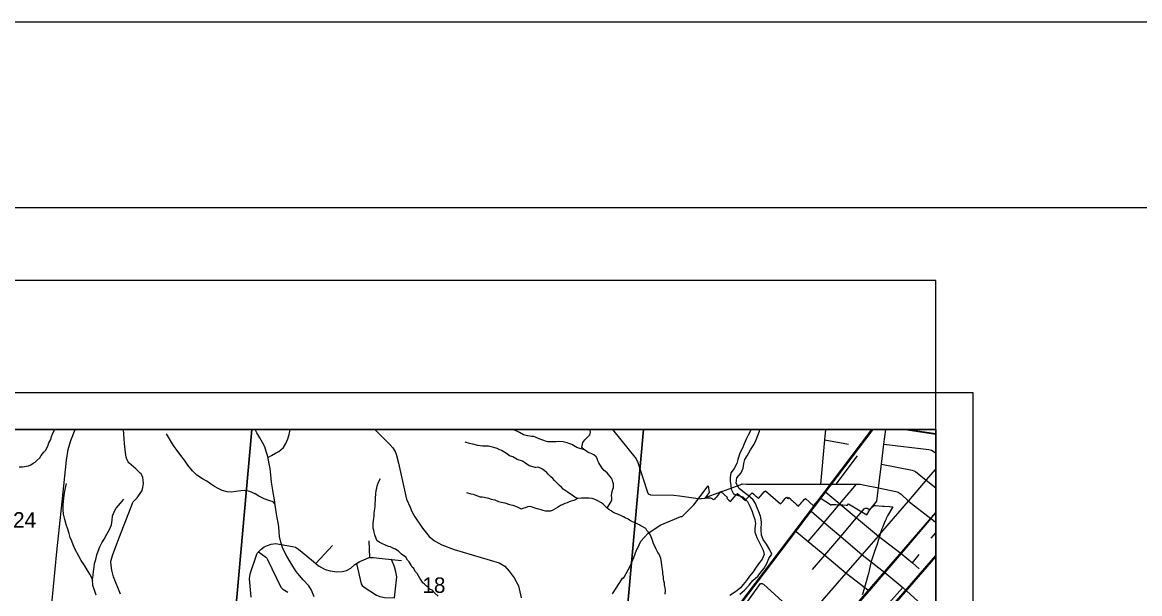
# Model space of a CAD drawing. Extents: x -8.2 to 38.5, y -0.1 to 21.9.
# Drawn here: x 6.498 to 9.514, y 20.321 to 21.864 of the extents above; entities that cross this region are included whole.
import ezdxf

# ---------------------------------------------------------------- set-up
doc = ezdxf.new("R2010")
doc.units = 0
for name, color, linetype in [('Default', 7, 'Continuous'), ('GM_X_Airport_Location_Class_1', 7, 'Continuous'), ('GM_X_County', 7, 'Continuous'), ('GM_X_County_Road_Text', 7, 'Continuous'), ('GM_X_Minor_River', 7, 'Continuous'), ('GM_X_Section', 7, 'Continuous'), ('GM_X_Township', 7, 'Continuous'), ('GM_X_Township_Subdivision_Text', 7, 'Continuous'), ('GM_X_Township_Text', 7, 'Continuous'), ('GM_X_US_Location', 7, 'Continuous')]:
    doc.layers.add(name, color=color, linetype=linetype)

msp = doc.modelspace()

# ---------------------------------------------------------------- linework, layer by layer
at = {"layer": 'Default'}
for points in [[(8.9634, 15.7165), (8.9634, 21.1673), (3.5768, 21.1673)], [(8.9634, 15.3136), (8.9634, 20.7535), (8.8842, 20.7645), (4.0666, 20.7645), (4.0665, 20.7635), (4.0467, 20.5533), (4.0404, 20.4649), (4.0302, 20.3597), (3.9961, 19.9817), (3.9436, 19.3979), (3.9289, 19.2353), (3.8854, 18.7517), (3.8472, 18.3279), (3.8449, 18.303), (3.8435, 18.2895), (3.8184, 18.0516), (3.7486, 17.3899)], [(8.091, 20.3209), (8.1173, 20.3612), (8.1189, 20.3639), (8.1204, 20.3632), (8.1223, 20.3664), (8.1391, 20.3959), (8.1483, 20.4192), (8.1558, 20.4393), (8.1564, 20.4405), (8.1588, 20.4438), (8.1679, 20.4634), (8.1875, 20.4849), (8.216, 20.504), (8.2199, 20.5066), (8.2759, 20.53), (8.2793, 20.5296), (8.3103, 20.5618), (8.3495, 20.6123), (8.3518, 20.5951), (8.3409, 20.5807), (8.3556, 20.5799), (8.3582, 20.5797), (8.3635, 20.5762), (8.365, 20.578), (8.3676, 20.5763), (8.3704, 20.5801), (8.3733, 20.5839), (8.3768, 20.5885), (8.3802, 20.593), (8.3837, 20.5975), (8.4013, 20.5816), (8.3996, 20.5793), (8.405, 20.5744), (8.4092, 20.5706), (8.425, 20.5883), (8.4285, 20.592), (8.4497, 20.5735), (8.4523, 20.5763), (8.4681, 20.594), (8.4724, 20.5902), (8.4766, 20.5864), (8.4808, 20.5826), (8.485, 20.5788), (8.5008, 20.5964), (8.5037, 20.5996), (8.5442, 20.5642), (8.5472, 20.5672), (8.5504, 20.5707), (8.5536, 20.5742), (8.5574, 20.5784), (8.5605, 20.5819), (8.5647, 20.578), (8.5673, 20.5809), (8.5713, 20.5773), (8.5716, 20.5771), (8.5737, 20.5752), (8.5758, 20.5733), (8.58, 20.5694), (8.5821, 20.5675), (8.5842, 20.5656), (8.5856, 20.5643), (8.5884, 20.5618), (8.5927, 20.5579), (8.5959, 20.5614), (8.599, 20.565), (8.6022, 20.5685), (8.6054, 20.572), (8.6086, 20.5755), (8.6116, 20.5786), (8.6336, 20.5591), (8.6526, 20.5799), (8.6568, 20.5767), (8.6772, 20.5637), (8.6816, 20.5608), (8.683, 20.5624), (8.6875, 20.5622), (8.6937, 20.5619), (8.7002, 20.5616), (8.7061, 20.5613), (8.7126, 20.561), (8.722, 20.5605), (8.7251, 20.5604), (8.7283, 20.5642), (8.7774, 20.534), (8.7804, 20.5385), (8.7868, 20.5499), (8.7971, 20.5596), (8.8013, 20.5594), (8.8196, 20.5582), (8.8244, 20.5578), (8.8384, 20.5569), (8.8474, 20.5563), (8.8331, 20.5318), (8.8299, 20.5241), (8.8287, 20.5211), (8.8285, 20.5206), (8.8243, 20.5124), (8.824, 20.5117), (8.8208, 20.5018), (8.8183, 20.4962), (8.8147, 20.4854), (8.8115, 20.4755), (8.8082, 20.4655), (8.805, 20.4555), (8.8017, 20.4454), (8.7985, 20.4356), (8.7896, 20.4082), (8.7869, 20.3963), (8.7824, 20.3757), (8.7822, 20.3758), (8.7785, 20.364), (8.7782, 20.3631), (8.7692, 20.3316), (8.7666, 20.3224), (8.7646, 20.3182)]]:
    msp.add_lwpolyline(points, dxfattribs=at)
for points in [[(7.1182, 20.7645), (6.1116, 20.7645), (6.0401, 20.072), (7.0485, 19.9899)], [(8.1752, 20.7645), (7.1182, 20.7645), (7.0485, 19.9899), (8.0944, 19.8749)], [(8.8806, 20.7645), (8.1752, 20.7645), (8.0944, 19.8749), (8.9634, 19.7388), (8.9634, 20.7526)], [(8.9634, 20.7526), (8.9634, 20.7645), (8.8806, 20.7645)], [(8.9634, 20.7535), (8.9634, 20.7645), (8.8842, 20.7645)]]:
    msp.add_lwpolyline(points, close=True, dxfattribs=at)
at = {"layer": 'GM_X_Airport_Location_Class_1'}
msp.add_line((8.9634, 20.5125), (8.9498, 20.5244), dxfattribs=at)
at = {"layer": 'GM_X_County'}
msp.add_lwpolyline([(1.5634, 21.3645), (33.5634, 21.3645), (33.5634, 0.3645), (1.5634, 0.3645)], close=True, dxfattribs=at)
at = {"layer": 'GM_X_Minor_River'}
msp.add_line((8.465, 20.7645), (8.4575, 20.7492), dxfattribs=at)
for points in [[(6.5496, 20.6947), (6.5563, 20.7033), (6.5614, 20.7092), (6.5635, 20.7138), (6.5674, 20.7201), (6.5699, 20.7284), (6.5751, 20.7382), (6.5773, 20.7461), (6.5813, 20.7566), (6.5859, 20.7645)], [(7.1801, 20.5644), (7.1755, 20.5696), (7.1634, 20.5733), (7.151, 20.5774), (7.1371, 20.585), (7.127, 20.5913), (7.1123, 20.5977), (7.0979, 20.6), (7.0881, 20.5995), (7.0743, 20.5975), (7.0625, 20.5959), (7.0515, 20.5962), (7.0379, 20.6003), (7.0267, 20.6059), (7.0169, 20.6111), (7.0064, 20.6182), (6.996, 20.6253), (6.9843, 20.6317), (6.9698, 20.6415), (6.9575, 20.6536), (6.9453, 20.6687), (6.9358, 20.6819), (6.9266, 20.695), (6.9163, 20.7078), (6.9085, 20.7191), (6.9019, 20.7291), (6.8957, 20.7395), (6.8877, 20.753)], [(7.2856, 20.3133), (7.2792, 20.331), (7.2719, 20.3429), (7.2563, 20.3593), (7.2467, 20.3702), (7.2371, 20.3818), (7.2283, 20.3961), (7.221, 20.4077), (7.2126, 20.4227), (7.2057, 20.4347), (7.2007, 20.4466), (7.1957, 20.4604), (7.1926, 20.476), (7.1914, 20.4886), (7.1902, 20.5016), (7.1886, 20.5141), (7.1866, 20.5267), (7.1846, 20.5374), (7.1826, 20.5489), (7.1806, 20.5611), (7.1787, 20.5745), (7.1764, 20.5893), (7.1744, 20.6012), (7.1727, 20.6122), (7.1711, 20.6225), (7.1698, 20.6328), (7.1689, 20.6424), (7.1674, 20.6591), (7.165, 20.6717), (7.163, 20.682), (7.1599, 20.695), (7.1567, 20.7054), (7.1528, 20.7176), (7.1467, 20.7296), (7.1394, 20.7427), (7.1317, 20.7562), (7.1268, 20.7645)], [(7.1613, 20.6893), (7.1709, 20.6948), (7.1813, 20.701), (7.1909, 20.7057), (7.2034, 20.7164), (7.2093, 20.7269), (7.2146, 20.7393), (7.2183, 20.751), (7.2209, 20.7643), (7.2209, 20.7645)], [(7.8789, 20.7455), (7.8725, 20.746), (7.8585, 20.7487), (7.8506, 20.7508), (7.8401, 20.7565), (7.8352, 20.7593), (7.8251, 20.7637), (7.8236, 20.7645)], [(8.0764, 20.5527), (8.0873, 20.5701), (8.089, 20.5746), (8.0892, 20.5799), (8.0887, 20.5864), (8.0894, 20.5928), (8.0903, 20.5977), (8.0924, 20.6033), (8.0934, 20.6079), (8.094, 20.6132), (8.0938, 20.6177), (8.0921, 20.6235), (8.0905, 20.6304), (8.0847, 20.6379), (8.0807, 20.6437), (8.0763, 20.6477), (8.0682, 20.6541), (8.0635, 20.66), (8.0603, 20.6651), (8.0571, 20.6705), (8.0546, 20.6752), (8.0518, 20.6803), (8.0504, 20.6849), (8.0472, 20.6911), (8.0406, 20.6967), (8.0358, 20.6992), (8.0309, 20.7009), (8.0257, 20.703), (8.0212, 20.7059), (8.0168, 20.7091), (8.0124, 20.7127), (8.0088, 20.7174), (8.0102, 20.7249), (8.0111, 20.7295), (8.0163, 20.7365), (8.0207, 20.7412), (8.0258, 20.7456), (8.0298, 20.7503), (8.0316, 20.7575), (8.0307, 20.7632), (8.0304, 20.7645)], [(8.4575, 20.7492), (8.452, 20.7387), (8.4461, 20.7258), (8.4417, 20.7141), (8.435, 20.701), (8.4298, 20.684), (8.4269, 20.6734), (8.4198, 20.6598), (8.4105, 20.6482), (8.4087, 20.635), (8.4089, 20.6251), (8.4102, 20.6137), (8.4116, 20.6034), (8.4174, 20.5911), (8.4306, 20.5867), (8.4427, 20.583), (8.4557, 20.5702), (8.462, 20.558), (8.4678, 20.5438), (8.471, 20.5342), (8.4753, 20.522), (8.4774, 20.5113), (8.4749, 20.4977), (8.4751, 20.4874), (8.4805, 20.4736), (8.4864, 20.4621), (8.4926, 20.4498), (8.4977, 20.4391), (8.5001, 20.4269), (8.4953, 20.4144), (8.4852, 20.4017), (8.4774, 20.3908), (8.4708, 20.3807), (8.4611, 20.3687), (8.4525, 20.3567), (8.4436, 20.3466), (8.4362, 20.3369), (8.4231, 20.3265), (8.4081, 20.3165)], [(8.4348, 20.3198), (8.4475, 20.3314), (8.4599, 20.3448), (8.47, 20.3572), (8.4831, 20.3687), (8.4924, 20.3807), (8.5002, 20.3908), (8.5073, 20.4032), (8.5132, 20.4164), (8.5214, 20.4284), (8.5159, 20.4403), (8.5067, 20.4549), (8.4975, 20.4676), (8.4931, 20.4791), (8.4919, 20.4935), (8.493, 20.5156), (8.4903, 20.5308), (8.4859, 20.5423), (8.4816, 20.5534), (8.4769, 20.5649), (8.4706, 20.5749), (8.4576, 20.5869), (8.4426, 20.5975), (8.4329, 20.6056), (8.4248, 20.6195), (8.4269, 20.6346), (8.4386, 20.6477), (8.4437, 20.6601), (8.4459, 20.673), (8.4487, 20.6836), (8.4542, 20.6938), (8.4636, 20.7103), (8.4734, 20.7253), (8.4789, 20.7366), (8.4833, 20.7483), (8.4877, 20.7608), (8.4891, 20.7645)], [(7.8831, 20.6618), (7.8662, 20.6663), (7.8535, 20.6754), (7.8479, 20.679), (7.8343, 20.6839), (7.822, 20.6907), (7.8133, 20.694), (7.8051, 20.7003), (7.7912, 20.7083), (7.7867, 20.71), (7.7796, 20.7132), (7.7709, 20.7165), (7.7569, 20.7196), (7.7478, 20.7202), (7.7406, 20.72), (7.7341, 20.7206), (7.7281, 20.7215), (7.7145, 20.725), (7.705, 20.7267), (7.6937, 20.7305)], [(8.0159, 20.7098), (8.0029, 20.7131), (7.995, 20.7164), (7.9906, 20.7189), (7.9813, 20.7239), (7.9734, 20.7272), (7.9689, 20.7289), (7.9576, 20.7313), (7.9451, 20.7322), (7.9394, 20.7317), (7.9322, 20.7316), (7.9272, 20.7314), (7.9162, 20.7319), (7.9106, 20.7332), (7.9057, 20.735), (7.9004, 20.7367), (7.893, 20.7397), (7.8789, 20.7455)], [(6.4895, 20.6637), (6.4986, 20.6642), (6.5043, 20.6648), (6.5097, 20.6654), (6.515, 20.6671), (6.5212, 20.6693), (6.5278, 20.6736), (6.5332, 20.6765), (6.5375, 20.6814), (6.5457, 20.688), (6.5496, 20.6947)], [(7.9983, 20.5783), (7.9901, 20.5814), (7.985, 20.5854), (7.9776, 20.5906), (7.9691, 20.5967), (7.9635, 20.6003), (7.9579, 20.6036), (7.9536, 20.6087), (7.9481, 20.6139), (7.9422, 20.6198), (7.9349, 20.627), (7.9298, 20.6329), (7.9247, 20.6369), (7.9173, 20.6441), (7.9126, 20.6492), (7.9074, 20.6532), (7.9019, 20.6576), (7.8952, 20.6609), (7.8899, 20.6627), (7.8818, 20.6616)], [(7.6209, 20.3146), (7.6116, 20.3225), (7.6043, 20.3307), (7.5983, 20.3339), (7.5938, 20.3389), (7.5882, 20.3425), (7.5842, 20.3476), (7.5797, 20.3504), (7.5764, 20.355), (7.5709, 20.3636), (7.5636, 20.3756), (7.5588, 20.3814), (7.5549, 20.3895), (7.5504, 20.3934), (7.5479, 20.3985), (7.5424, 20.4077), (7.538, 20.4121), (7.5333, 20.4198), (7.5213, 20.4281), (7.5147, 20.4355), (7.5057, 20.4415), (7.4982, 20.4444), (7.4922, 20.4476), (7.4865, 20.4493), (7.4782, 20.4529), (7.47, 20.4562), (7.461, 20.461), (7.4554, 20.465), (7.4532, 20.4708), (7.4501, 20.48), (7.448, 20.4873), (7.447, 20.4919), (7.4456, 20.4988), (7.4456, 20.5121), (7.4462, 20.5182), (7.4467, 20.5254), (7.4476, 20.5307), (7.4482, 20.539), (7.4491, 20.5439), (7.4497, 20.5515), (7.4502, 20.5565), (7.4508, 20.5652), (7.4515, 20.5743), (7.4512, 20.5797), (7.4527, 20.591), (7.4533, 20.5998), (7.455, 20.6062), (7.4559, 20.6123), (7.4584, 20.6202), (7.4612, 20.6258), (7.4648, 20.6326)], [(6.6883, 20.3571), (6.6875, 20.3603), (6.6802, 20.3741), (6.6736, 20.3857), (6.6649, 20.3996), (6.6575, 20.4115), (6.6499, 20.4247), (6.6415, 20.4393), (6.6354, 20.4531), (6.6322, 20.4631), (6.6279, 20.4735), (6.6247, 20.4842), (6.6212, 20.4957), (6.6166, 20.508), (6.6127, 20.5214), (6.6096, 20.5359), (6.6084, 20.5481), (6.6087, 20.561), (6.6093, 20.5705), (6.6103, 20.58), (6.6118, 20.5925), (6.6139, 20.6027), (6.6177, 20.6193)], [(7.6973, 20.5949), (7.709, 20.5911), (7.7154, 20.5898), (7.7199, 20.5885), (7.7267, 20.5853), (7.7343, 20.5832), (7.7392, 20.5827), (7.7452, 20.5817), (7.7566, 20.5795), (7.7634, 20.5767), (7.7739, 20.5745), (7.7834, 20.5708), (7.7913, 20.5686), (7.8004, 20.5669), (7.8132, 20.5627), (7.8219, 20.5606), (7.8335, 20.5557), (7.8448, 20.5504), (7.8618, 20.5563)], [(6.6978, 20.317), (6.6928, 20.3309), (6.689, 20.3435), (6.6882, 20.3595), (6.6892, 20.3709), (6.6907, 20.3822), (6.692, 20.3921), (6.6934, 20.4027), (6.6964, 20.414), (6.6997, 20.4261), (6.703, 20.4363), (6.7078, 20.4483), (6.713, 20.4588), (6.719, 20.4686), (6.7265, 20.4821), (6.734, 20.4945), (6.7393, 20.5072), (6.7407, 20.5201), (6.7421, 20.5307), (6.7454, 20.5409), (6.7521, 20.5526), (6.7631, 20.5656), (6.7725, 20.5771)], [(8.2337, 20.3205), (8.2341, 20.33), (8.2333, 20.3376), (8.2317, 20.3449), (8.2311, 20.3498), (8.2298, 20.3564), (8.2292, 20.3609), (8.2287, 20.367), (8.2272, 20.3755), (8.2266, 20.3804), (8.2257, 20.3865), (8.2251, 20.3919), (8.2239, 20.3995), (8.2234, 20.4053), (8.2221, 20.4121), (8.2216, 20.4167), (8.2191, 20.4233), (8.2174, 20.4279), (8.2135, 20.433), (8.211, 20.4381), (8.2078, 20.4435), (8.2054, 20.4501), (8.2022, 20.4563), (8.2002, 20.4625), (8.197, 20.4702), (8.1957, 20.4752), (8.1915, 20.483), (8.1886, 20.4876), (8.1842, 20.492), (8.181, 20.4974), (8.168, 20.5044), (8.1628, 20.5073), (8.1542, 20.5115), (8.1452, 20.5156), (8.1374, 20.5198), (8.133, 20.5226), (8.1255, 20.526), (8.1211, 20.5288), (8.1155, 20.5317), (8.1087, 20.5346), (8.1024, 20.5368), (8.0975, 20.5385), (8.0923, 20.5414), (8.0875, 20.545), (8.0808, 20.5491), (8.0764, 20.5527), (8.0713, 20.5582), (8.0658, 20.5634), (8.061, 20.5666), (8.0513, 20.5724), (8.0416, 20.5766), (8.036, 20.5787), (8.0269, 20.5795), (8.0223, 20.5793), (8.014, 20.5796), (8.0075, 20.5795), (7.9964, 20.5781), (7.991, 20.5749), (7.9744, 20.5691), (7.969, 20.5667), (7.9621, 20.5647), (7.9571, 20.5626), (7.9505, 20.5598), (7.9423, 20.5545), (7.9361, 20.5509), (7.9299, 20.547), (7.9241, 20.5442), (7.9191, 20.544), (7.91, 20.5444), (7.9036, 20.5462), (7.8984, 20.5483), (7.8927, 20.5497), (7.8882, 20.5506), (7.8826, 20.5528), (7.8773, 20.5545), (7.8725, 20.5559), (7.8668, 20.5565), (7.8618, 20.5563)]]:
    msp.add_lwpolyline(points, dxfattribs=at)
at = {"layer": 'GM_X_Section'}
msp.add_lwpolyline([(0.0634, -0.1355), (34.0634, -0.1355), (34.0634, 21.8645), (0.0634, 21.8645)], close=True, dxfattribs=at)
msp.add_lwpolyline([(8.9634, 15.3136), (8.9634, 20.7645), (2.1634, 20.7645), (2.1634, 13.9645)], dxfattribs=at)
at = {"layer": 'GM_X_Township'}
for p, q in [((2.0634, 20.8645), (9.0634, 20.8645)), ((9.0634, 20.8645), (9.0634, 13.8645)), ((2.1634, 20.7645), (8.9634, 20.7645)), ((8.9634, 20.7645), (8.9634, 13.9645))]:
    msp.add_line(p, q, dxfattribs=at)
at = {"layer": 'GM_X_Township_Subdivision_Text'}
for p, q in [((8.6642, 20.7371), (8.7282, 20.7256)), ((8.6944, 20.617), (8.7527, 20.6936)), ((8.951, 20.4715), (8.9634, 20.4858)), ((7.2908, 20.4028), (7.3359, 20.4514)), ((7.4358, 20.4189), (7.434, 20.4641)), ((8.9004, 20.4046), (8.9187, 20.4274))]:
    msp.add_line(p, q, dxfattribs=at)
for points in [[(6.7631, 20.32), (6.7447, 20.3674), (6.7399, 20.3854), (6.738, 20.3987), (6.7372, 20.4062), (6.7374, 20.409), (6.7378, 20.4118), (6.743, 20.4275), (6.7608, 20.4752), (6.7966, 20.568), (6.7977, 20.5698), (6.8068, 20.5782), (6.8087, 20.5805), (6.8197, 20.5971), (6.8214, 20.5999), (6.824, 20.6086), (6.8254, 20.6192), (6.8248, 20.6276), (6.8236, 20.6352), (6.8221, 20.6395), (6.8204, 20.6429), (6.819, 20.6448), (6.8164, 20.6472), (6.8049, 20.6585), (6.7857, 20.6752), (6.7838, 20.6774), (6.7811, 20.6832), (6.7789, 20.6901), (6.7766, 20.703), (6.7739, 20.7274), (6.771, 20.7645)], [(8.6305, 20.3864), (8.6638, 20.4254), (8.707, 20.476), (8.7499, 20.5262), (8.7712, 20.5511), (8.7719, 20.5517), (8.7734, 20.5524), (8.775, 20.5527), (8.7769, 20.5528), (8.7781, 20.5524), (8.7858, 20.5475), (8.8044, 20.5711), (8.8047, 20.5717), (8.8048, 20.5724), (8.8091, 20.6071), (8.8171, 20.6715), (8.8237, 20.725), (8.8285, 20.7645)], [(8.6534, 20.6171), (8.6642, 20.7371), (8.6667, 20.7645)], [(8.8237, 20.725), (8.9451, 20.7104), (8.9519, 20.7088), (8.9594, 20.7041), (8.9634, 20.7007)], [(8.8171, 20.6715), (8.9001, 20.6547), (8.9046, 20.6534), (8.9091, 20.6511), (8.938, 20.6277), (8.9634, 20.6072)], [(8.6195, 20.4624), (8.6605, 20.5112), (8.6628, 20.514), (8.7048, 20.5638), (8.7494, 20.6169)], [(8.6667, 20.5956), (8.7048, 20.5638), (8.7499, 20.5262), (8.8087, 20.4772), (8.87, 20.4296)], [(8.627, 20.5447), (8.6628, 20.514), (8.707, 20.476), (8.7648, 20.4265), (8.8257, 20.379)], [(8.5869, 20.4896), (8.6195, 20.4624), (8.6638, 20.4254), (8.7219, 20.377), (8.7839, 20.329)], [(7.1156, 20.3124), (7.1117, 20.3612), (7.1123, 20.3684), (7.1145, 20.3782), (7.1312, 20.4278), (7.1331, 20.4316), (7.1358, 20.4345), (7.1382, 20.4371), (7.1433, 20.4419), (7.1511, 20.4478), (7.1603, 20.452), (7.1699, 20.4552), (7.1762, 20.4565), (7.1821, 20.4567), (7.2279, 20.4493), (7.2354, 20.4468), (7.2436, 20.4416), (7.2789, 20.4125), (7.2908, 20.4028), (7.2978, 20.3971), (7.3158, 20.3871), (7.3294, 20.3832), (7.3468, 20.3808), (7.3627, 20.3811), (7.3735, 20.3838), (7.3854, 20.3903), (7.396, 20.3999), (7.4001, 20.4026), (7.4092, 20.4086), (7.4196, 20.4133), (7.4342, 20.4189), (7.4358, 20.4189), (7.4459, 20.4189), (7.4694, 20.4164), (7.4949, 20.4138), (7.5221, 20.411)], [(7.1358, 20.4345), (7.1552, 20.4201), (7.158, 20.4175), (7.1592, 20.4158), (7.1603, 20.4139), (7.1959, 20.3391), (7.1993, 20.3353), (7.2015, 20.3337), (7.2146, 20.3258)], [(8.87, 20.4296), (8.9004, 20.4046), (8.919, 20.3888)], [(7.4001, 20.4026), (7.4127, 20.3477), (7.4156, 20.3439), (7.4212, 20.3388), (7.4544, 20.3173), (7.4634, 20.3136), (7.4759, 20.3113), (7.5024, 20.3098), (7.5087, 20.3673), (7.5068, 20.3803), (7.5026, 20.3941), (7.4949, 20.4138)], [(8.8257, 20.379), (8.8746, 20.3382), (8.9346, 20.2833)], [(8.373, 20.1814), (8.3942, 20.2118), (8.4269, 20.2586), (8.4613, 20.3078), (8.4903, 20.3493)], [(8.4903, 20.3493), (8.4917, 20.3494), (8.4935, 20.3494), (8.4951, 20.3489), (8.4963, 20.3485), (8.499, 20.3468), (8.5906, 20.2633)], [(8.7247, 20.1619), (8.8056, 20.2603), (8.8746, 20.3382)]]:
    msp.add_lwpolyline(points, dxfattribs=at)
at = {"layer": 'GM_X_Township_Text'}
for p, q in [((8.938, 20.6277), (8.9634, 20.6575)), ((8.9634, 20.5394), (8.9498, 20.5244))]:
    msp.add_line(p, q, dxfattribs=at)
for points in [[(6.7147, 19.7335), (6.7082, 19.7459), (6.6861, 19.7933), (6.6396, 19.8893), (6.6223, 19.9239), (6.6086, 19.955), (6.5997, 19.9767), (6.5891, 20.0088), (6.5807, 20.0402), (6.575, 20.0631), (6.5678, 20.1173), (6.5658, 20.1551), (6.5674, 20.2022), (6.5749, 20.2632), (6.578, 20.2937), (6.5914, 20.4341), (6.6057, 20.5698), (6.6177, 20.6816), (6.6222, 20.7111), (6.6291, 20.7348), (6.6413, 20.7645)], [(7.4494, 20.7645), (7.4898, 20.7241), (7.4987, 20.7151), (7.5048, 20.7053), (7.5077, 20.6982), (7.5117, 20.6815), (7.5119, 20.6806)], [(8.0912, 20.7645), (8.1546, 20.6856), (8.1597, 20.676), (8.1855, 20.5954), (8.1877, 20.5915), (8.1934, 20.5884), (8.2568, 20.5878), (8.2723, 20.586), (8.3287, 20.578), (8.3306, 20.5783)], [(7.5119, 20.6806), (7.5135, 20.6737), (7.5356, 20.5763), (7.5452, 20.555), (7.5488, 20.5455), (7.5578, 20.5287), (7.5747, 20.5042), (7.5752, 20.5034)], [(8.6002, 20.2562), (8.6105, 20.2484), (8.7219, 20.377), (8.7648, 20.4265), (8.8087, 20.4772), (8.8094, 20.478), (8.8902, 20.5717), (8.9362, 20.6257), (8.938, 20.6277)], [(8.3306, 20.5783), (8.339, 20.5797), (8.3418, 20.5808), (8.3562, 20.5865), (8.4353, 20.6156), (8.4407, 20.6178), (8.4525, 20.6175), (8.4535, 20.6175)], [(8.4535, 20.6175), (8.4677, 20.6175), (8.6534, 20.6171), (8.6737, 20.617)], [(8.6737, 20.617), (8.6919, 20.617), (8.6944, 20.617), (8.7494, 20.6169), (8.7592, 20.6168), (8.7724, 20.6147), (8.8091, 20.6071), (8.856, 20.5974), (8.8624, 20.5953), (8.8703, 20.5898), (8.8902, 20.5717), (8.9498, 20.5244)], [(8.9498, 20.5244), (8.87, 20.4296), (8.8257, 20.379), (8.7839, 20.329), (8.7587, 20.3005), (8.6713, 20.1975), (8.6446, 20.168), (8.6328, 20.1549)], [(7.5752, 20.5034), (7.5786, 20.4985), (7.5962, 20.476), (7.6112, 20.464), (7.6301, 20.4538), (7.6635, 20.4408), (7.7854, 20.4048), (7.8003, 20.3961), (7.8125, 20.3825), (7.8257, 20.3643), (7.8372, 20.3424), (7.8447, 20.3099)]]:
    msp.add_lwpolyline(points, dxfattribs=at)
at = {"layer": 'GM_X_US_Location'}
for points in [[(8.3, 20.1157), (8.6569, 20.5872), (8.7911, 20.7645)], [(8.3019, 20.1142), (8.6588, 20.5857), (8.7942, 20.7645)], [(8.2344, 19.6876), (8.3285, 19.8213), (8.3473, 19.8453), (8.6355, 20.1607), (8.9634, 20.541)], [(7.5778, 18.8354), (7.6076, 18.8584), (7.6215, 18.8707), (7.6436, 18.8896), (7.6518, 18.8987), (7.6593, 18.9076), (7.6907, 18.9438), (7.8035, 19.0752), (7.9664, 19.2661), (8.0256, 19.3336), (8.093, 19.4131), (8.2198, 19.5608), (8.2705, 19.6196), (8.3405, 19.7009), (8.4436, 19.8206), (8.7333, 20.1588), (8.9634, 20.425)], [(7.5791, 18.8333), (7.6037, 18.8523), (7.6454, 18.8879), (7.6536, 18.8971), (7.6612, 18.9059), (7.6926, 18.9422), (7.8054, 19.0736), (7.9683, 19.2645), (8.0275, 19.332), (8.0949, 19.4114), (8.2217, 19.5592), (8.2724, 19.618), (8.3424, 19.6992), (8.4455, 19.819), (8.7352, 20.1572), (8.9634, 20.4212)]]:
    msp.add_lwpolyline(points, dxfattribs=at)

# ---------------------------------------------------------------- texts
at = {"layer": 'GM_X_County_Road_Text'}
for s, p in [('24', (6.4734, 20.4997)), ('18', (7.578, 20.3236))]:
    msp.add_text(s, height=0.04186, rotation=0, dxfattribs=at).set_placement(p)

doc.saveas('drawing.dxf')
